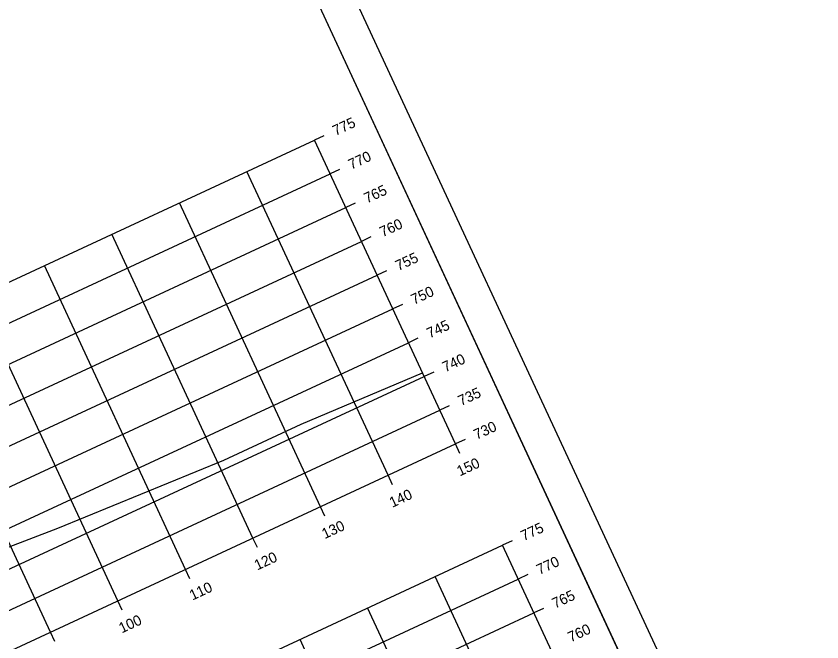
# Model space of a CAD drawing. Extents: x 1354696 to 1366163, y 660729 to 670380.
# Drawn here: x 1355159.5 to 1355267.8, y 664868.5 to 664952.5 of the extents above; entities that cross this region are included whole.
import ezdxf

# ---------------------------------------------------------------- set-up
doc = ezdxf.new("R2010")
doc.units = 0
for name, color, linetype in [('R_Axis', 7, 'Continuous'), ('R_Axis Annot', 7, 'Continuous'), ('R_Border', 7, 'Continuous'), ('R_Exist Surface', 7, 'Continuous'), ('R_Grid', 7, 'Continuous'), ('R_No Plot', 7, 'Continuous')]:
    doc.layers.add(name, color=color, linetype=linetype)

msp = doc.modelspace()

# ---------------------------------------------------------------- linework, layer by layer
at = {"layer": 'R_Axis'}
for p, q in [((1355200.88, 664936.46), (1355199.61, 664935.87)), ((1355218.56, 664895.06), (1355199.61, 664935.87)), ((1355202.99, 664931.93), (1355201.72, 664931.34)), ((1355205.09, 664927.39), (1355203.82, 664926.8)), ((1355207.2, 664922.86), (1355205.93, 664922.27)), ((1355209.3, 664918.32), (1355208.03, 664917.73)), ((1355211.41, 664913.79), (1355210.14, 664913.2)), ((1355213.51, 664909.25), (1355212.24, 664908.66)), ((1355215.62, 664904.72), (1355214.35, 664904.13)), ((1355217.72, 664900.18), (1355216.45, 664899.59)), ((1354946.46, 664768.73), (1355218.56, 664895.06)), ((1355219.83, 664895.65), (1355218.56, 664895.06)), ((1355219.15, 664893.79), (1355218.56, 664895.06)), ((1355210.08, 664889.58), (1355209.49, 664890.85)), ((1355201.01, 664885.36), (1355200.42, 664886.63)), ((1355191.94, 664881.15), (1355191.35, 664882.42)), ((1355226.15, 664882.04), (1355224.88, 664881.45)), ((1355245.93, 664836.1), (1355224.88, 664881.45)), ((1355182.87, 664876.94), (1355182.28, 664878.21)), ((1355228.25, 664877.51), (1355226.98, 664876.92)), ((1355173.8, 664872.73), (1355173.21, 664874)), ((1355230.36, 664872.97), (1355229.09, 664872.38)), ((1355164.73, 664868.52), (1355164.14, 664869.79))]:
    msp.add_line(p, q, dxfattribs=at)
at = {"layer": 'R_Border'}
msp.add_line((1355261.77, 664821.41), (1355175.25, 665007.76), dxfattribs=at)
at = {"layer": 'R_Exist Surface'}
msp.add_lwpolyline([(1355154.73, 664879.78), (1355165.13, 664883.73), (1355187.43, 664892.88), (1355197.81, 664897.7), (1355214.12, 664904.62)], dxfattribs=at)
at = {"layer": 'R_Grid'}
for p, q in [((1354927.51, 664809.54), (1355199.61, 664935.87)), ((1355218.56, 664895.06), (1355199.61, 664935.87)), ((1355209.49, 664890.85), (1355190.54, 664931.66)), ((1354929.61, 664805.01), (1355201.72, 664931.34)), ((1355200.42, 664886.63), (1355181.47, 664927.45)), ((1354931.72, 664800.47), (1355203.82, 664926.8)), ((1355191.35, 664882.42), (1355172.4, 664923.24)), ((1354933.82, 664795.94), (1355205.93, 664922.27)), ((1355182.28, 664878.21), (1355163.33, 664919.03)), ((1354935.93, 664791.4), (1355208.03, 664917.73)), ((1355173.21, 664874), (1355154.26, 664914.82)), ((1354938.03, 664786.87), (1355210.14, 664913.2)), ((1355164.14, 664869.79), (1355145.19, 664910.61)), ((1354940.14, 664782.33), (1355212.24, 664908.66)), ((1354942.24, 664777.8), (1355214.35, 664904.13)), ((1354944.35, 664773.26), (1355216.45, 664899.59)), ((1354946.46, 664768.73), (1355218.56, 664895.06)), ((1354952.77, 664755.12), (1355224.88, 664881.45)), ((1355245.93, 664836.1), (1355224.88, 664881.45)), ((1354954.88, 664750.59), (1355226.98, 664876.92)), ((1355236.86, 664831.89), (1355215.81, 664877.24)), ((1355227.79, 664827.68), (1355206.74, 664873.03)), ((1354956.98, 664746.05), (1355229.09, 664872.38)), ((1355218.72, 664823.47), (1355197.67, 664868.82))]:
    msp.add_line(p, q, dxfattribs=at)
at = {"layer": 'R_No Plot'}
for points in [[(1354875.58, 664872.92), (1355177.92, 665013.29), (1355267.76, 664819.79), (1354965.42, 664679.42)], [(1355100.64, 664973.12), (1355118.44, 664981.38), (1355122.6, 664972.42), (1355137.21, 664979.21), (1355158.25, 664988.98), (1355170.22, 664963.49), (1355191.27, 664973.26), (1355261.77, 664821.41), (1354974.99, 664688.26), (1354888.47, 664874.62)]]:
    msp.add_lwpolyline(points, close=True, dxfattribs=at)

# ---------------------------------------------------------------- texts
at = {"layer": 'R_Axis Annot'}
for s, p in [('775', (1355202.44, 664936.42)), ('770', (1355204.55, 664931.88)), ('765', (1355206.66, 664927.35)), ('760', (1355208.76, 664922.81)), ('755', (1355210.87, 664918.28)), ('750', (1355212.97, 664913.74)), ('745', (1355215.08, 664909.21)), ('740', (1355217.18, 664904.67)), ('735', (1355219.29, 664900.14)), ('730', (1355221.39, 664895.6)), ('150', (1355219.13, 664890.69)), ('140', (1355210.06, 664886.48)), ('130', (1355200.99, 664882.27)), ('775', (1355227.71, 664882)), ('120', (1355191.92, 664878.06)), ('770', (1355229.82, 664877.46)), ('110', (1355183.21, 664874.02)), ('765', (1355231.92, 664872.93)), ('100', (1355173.73, 664869.61)), ('760', (1355234.03, 664868.39))]:
    msp.add_text(s, height=1.4, rotation=24.9042, dxfattribs=at).set_placement(p)

doc.saveas('drawing.dxf')
